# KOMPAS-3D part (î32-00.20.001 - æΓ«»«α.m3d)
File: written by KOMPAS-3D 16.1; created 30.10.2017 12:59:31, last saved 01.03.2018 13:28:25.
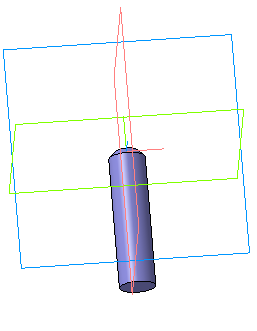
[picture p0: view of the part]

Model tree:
1. Эскиз:12
2. Операция вращения:1
     Угол 1 = 360
3. Фаска:5
     Угол = 45; Длина 1 = 1.5; Длина 2 = 1.5

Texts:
  Полипропилен  ГОСТ 26996-86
